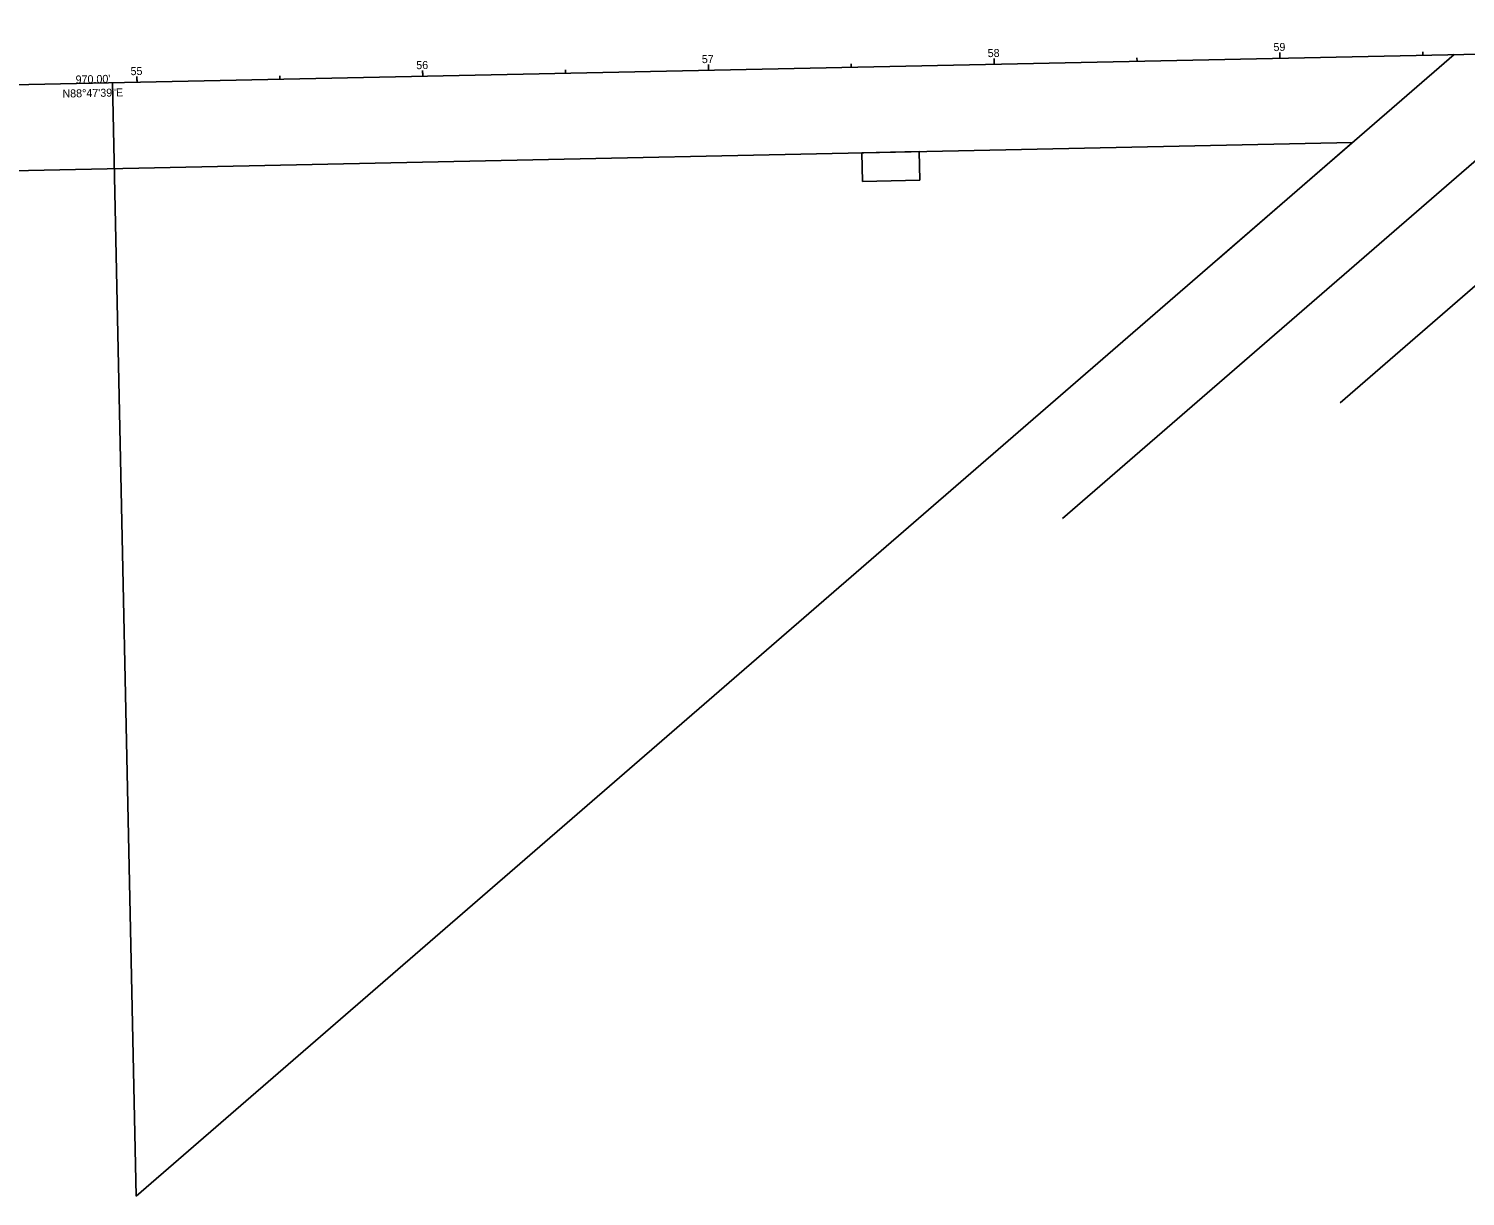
# Model space of a CAD drawing. Extents: x 2402033 to 2407434, y 498266 to 500417.
# Drawn here: x 2402497 to 2402999, y 498266 to 498675 of the extents above; entities that cross this region are included whole.
import ezdxf

# ---------------------------------------------------------------- set-up
doc = ezdxf.new("R2010")
doc.units = 0
for name, color, linetype in [('BR_P_Rail_Object', 7, 'Continuous'), ('DR_P_Inlet_Protection', 7, 'Continuous'), ('DR_X_Cells', 7, 'Continuous'), ('DR_X_Elev_Flow', 7, 'Continuous'), ('PV_P_EOP', 7, 'Continuous'), ('PV_P_Shoulder', 7, 'Continuous'), ('PV_X_EOP', 7, 'Continuous'), ('RD_P_GR_Lt', 7, 'Continuous'), ('RD_X_RR_Cells', 7, 'Continuous'), ('SN_X_Public', 7, 'Continuous'), ('UT_X_Cable_TV_FO', 7, 'Continuous'), ('UT_X_Electric_Cells', 7, 'Continuous'), ('UT_X_Gas_Cells', 7, 'Continuous'), ('UT_X_Telecom_Cells', 7, 'Continuous')]:
    doc.layers.add(name, color=color, linetype=linetype)

msp = doc.modelspace()

# ---------------------------------------------------------------- linework, layer by layer
at = {"layer": 'PV_P_EOP'}
msp.add_line((2402034.69, 498645.41), (2403004.47, 498665.82), dxfattribs=at)
msp.add_lwpolyline([(2402858.39, 498503.28), (2403052.97, 498671.81), (2404213.72, 499677.16)], dxfattribs=at)
at = {"layer": 'PV_P_Shoulder'}
for p, q in [((2402734.53, 498660.14), (2402734.51, 498661.34)), ((2402834.51, 498662.24), (2402834.49, 498663.44)), ((2402934.49, 498664.35), (2402934.46, 498665.55)), ((2402534.58, 498655.93), (2402534.54, 498657.93)), ((2402634.56, 498658.03), (2402634.53, 498659.23))]:
    msp.add_line(p, q, dxfattribs=at)
at = {"layer": 'PV_X_EOP'}
for p, q in [((2402788.23, 498631.26), (2402808.23, 498631.68)), ((2402788.44, 498621.26), (2402788.23, 498631.26)), ((2402808.23, 498631.68), (2402808.44, 498621.69)), ((2402808.44, 498621.69), (2402788.44, 498621.26))]:
    msp.add_line(p, q, dxfattribs=at)
at = {"layer": 'RD_P_GR_Lt'}
for p, q in [((2402984.48, 498665.4), (2402984.45, 498666.6)), ((2402734.53, 498660.14), (2402734.49, 498662.14)), ((2402784.52, 498661.19), (2402784.5, 498662.39)), ((2402834.51, 498662.24), (2402834.47, 498664.24)), ((2402884.5, 498663.3), (2402884.47, 498664.49)), ((2402934.49, 498664.35), (2402934.45, 498666.35)), ((2402534.58, 498655.93), (2402534.54, 498657.93)), ((2402584.57, 498656.98), (2402584.54, 498658.18)), ((2402634.56, 498658.03), (2402634.51, 498660.03)), ((2402684.54, 498659.09), (2402684.52, 498660.29))]:
    msp.add_line(p, q, dxfattribs=at)
at = {"layer": 'RD_X_RR_Cells'}
for p, q in [((2402955.58, 498543.8), (2403063.62, 498637.38)), ((2402912.37, 498593.69), (2402959.93, 498634.88))]:
    msp.add_line(p, q, dxfattribs=at)
at = {"layer": 'SN_X_Public'}
msp.add_line((2402534.58, 498655.93), (2402534.55, 498657.13), dxfattribs=at)
at = {"layer": 'UT_X_Cable_TV_FO'}
for p, q in [((2402995.43, 498665.63), (2402534.23, 498266.17)), ((2402534.23, 498266.17), (2402526.03, 498655.75))]:
    msp.add_line(p, q, dxfattribs=at)
at = {"layer": 'UT_X_Electric_Cells'}
msp.add_line((2402235.27, 498619.62), (2402959.93, 498634.88), dxfattribs=at)

# ---------------------------------------------------------------- texts
at = {"layer": 'BR_P_Rail_Object'}
msp.add_text('N88°47\'39"E', height=2.8, rotation=1.2059, dxfattribs=at).set_placement((2402508.5, 498650.58))
at = {"layer": 'DR_P_Inlet_Protection'}
msp.add_text('N88°47\'39"E', height=2.8, rotation=1.2059, dxfattribs=at).set_placement((2402508.5, 498650.58))
at = {"layer": 'DR_X_Cells'}
msp.add_text('N88°47\'39"E', height=2.8, rotation=1.2059, dxfattribs=at).set_placement((2402508.5, 498650.58))
at = {"layer": 'DR_X_Elev_Flow'}
msp.add_text("970.00'", height=2.8, rotation=1.2059, dxfattribs=at).set_placement((2402513.1, 498655.52))
at = {"layer": 'PV_P_Shoulder'}
msp.add_text('55', height=2.8, rotation=1.2059, dxfattribs=at).set_placement((2402532.32, 498658.43))
at = {"layer": 'RD_P_GR_Lt'}
for s, p in [('58', (2402832.27, 498664.74)), ('59', (2402932.27, 498666.85)), ('56', (2402632.3, 498660.53)), ('57', (2402732.23, 498662.64)), ('55', (2402532.32, 498658.43))]:
    msp.add_text(s, height=2.8, rotation=1.2059, dxfattribs=at).set_placement(p)
at = {"layer": 'UT_X_Gas_Cells'}
msp.add_text("970.00'", height=2.8, rotation=1.2059, dxfattribs=at).set_placement((2402513.1, 498655.52))
at = {"layer": 'UT_X_Telecom_Cells'}
msp.add_text("970.00'", height=2.8, rotation=1.2059, dxfattribs=at).set_placement((2402513.1, 498655.52))

doc.saveas('drawing.dxf')
